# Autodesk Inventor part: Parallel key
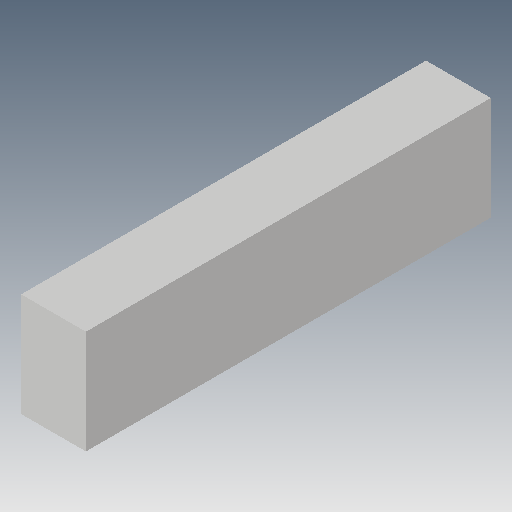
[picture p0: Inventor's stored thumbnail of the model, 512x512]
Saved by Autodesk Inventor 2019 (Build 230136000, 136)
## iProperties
Created: 2016-05
Part Number: Parallel key
Material: Generic
Document SubType Name: Modeling
Designer: CADCIM
Density: 1 g/cm^3
Appearance: Default
Author: CADCIM
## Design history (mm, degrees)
sketch "Sketch1"
  geometry: L1 (0, 0)-(16, 0); L2 (16, 0)-(16, -62.5); L3 (16, -62.5)-(0, -62.5); L4 (0, -62.5)-(0, 0)
  constraints: 8 end point, 2 parallel, 1 horizontal, 1 perpendicular
  dimensions: "d0" = 62.5 distance of L3.end L1.start; "d1" = 16 distance of L2.end L3.end
extrude "Extrusion1" new body sketch "Sketch1" distance "d2" = 10; taper "d3" = 0 deg
body "Solid1"
